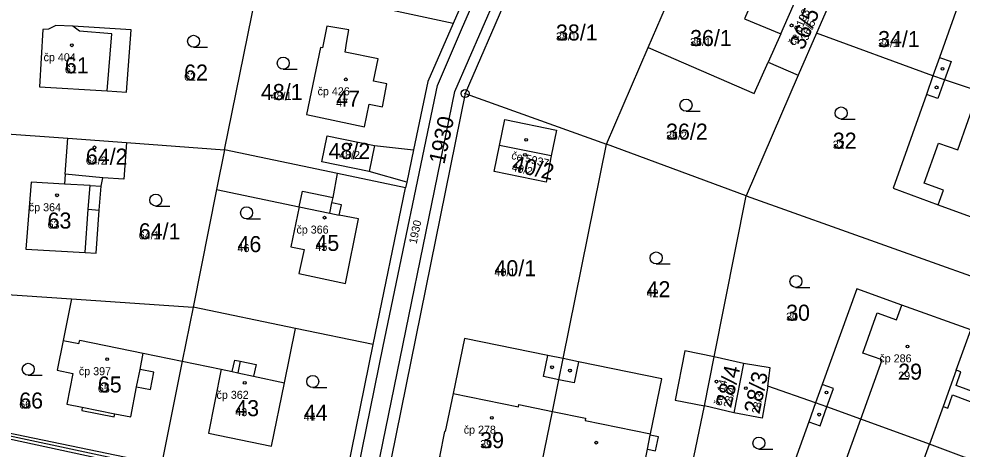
# Model space of a CAD drawing. Extents: x -763628 to -761565, y -976033 to -973833.
# Drawn here: x -762540.9 to -762423.1, y -974916.1 to -974862.4 of the extents above; entities that cross this region are included whole.
import ezdxf

# ---------------------------------------------------------------- set-up
doc = ezdxf.new("R2010")
doc.units = 0
for name, color, linetype in [('KN_cisla parcel 1000', 7, 'Continuous'), ('KN_cisla parcel 500', 7, 'Continuous'), ('KN_cisla popisna 500', 7, 'Continuous'), ('KN_hranice parcel', 7, 'Continuous'), ('KN_vecna bremena', 7, 'Continuous'), ('KN_vnitrni kresba parcel', 7, 'Continuous'), ('KN_znacky bodu BP', 7, 'Continuous'), ('KN_znacky budov', 7, 'Continuous'), ('KN_znacky kultur', 7, 'Continuous')]:
    doc.layers.add(name, color=color, linetype=linetype)

msp = doc.modelspace()

# ---------------------------------------------------------------- linework, layer by layer
at = {"layer": 'KN_hranice parcel'}
for p, q in [((-762479.49, -974846.12), (-762486.68, -974862.98)), ((-762475.48, -974849.36), (-762485.19, -974871.73)), ((-762462.34, -974865.99), (-762457.65, -974855.12)), ((-762486.68, -974862.98), (-762510.87, -974857.78)), ((-762445.75, -974864.29), (-762443.41, -974858.87)), ((-762515.26, -974878.75), (-762511.23, -974859.12)), ((-762439.69, -974860.48), (-762441.33, -974864.2)), ((-762445.75, -974864.29), (-762447.35, -974867.83)), ((-762441.33, -974864.2), (-762443.6, -974869.45)), ((-762426.77, -974869.52), (-762441.33, -974864.2)), ((-762467.55, -974878.06), (-762462.34, -974865.99)), ((-762447.35, -974867.83), (-762443.6, -974869.45)), ((-762443.6, -974869.45), (-762450.11, -974884.49)), ((-762485.19, -974871.73), (-762467.55, -974878.06)), ((-762543.9, -974876.64), (-762534.82, -974877.31)), ((-762535.16, -974881.79), (-762534.82, -974877.31)), ((-762534.82, -974877.31), (-762527.47, -974877.85)), ((-762527.47, -974877.85), (-762515.26, -974878.75)), ((-762515.26, -974878.75), (-762516.25, -974883.71)), ((-762501.13, -974881.7), (-762515.26, -974878.75)), ((-762491.64, -974878.76), (-762492.48, -974882.79)), ((-762472.96, -974904.8), (-762467.55, -974878.06)), ((-762450.11, -974884.49), (-762467.55, -974878.06)), ((-762530.44, -974882.24), (-762535.16, -974881.79)), ((-762492.63, -974883.48), (-762501.13, -974881.7)), ((-762516.25, -974883.71), (-762519.16, -974898.38)), ((-762496.67, -974903.06), (-762492.63, -974883.48)), ((-762492.48, -974882.79), (-762492.63, -974883.48)), ((-762454.1, -974904.59), (-762450.11, -974884.49)), ((-762545.41, -974896.62), (-762534.35, -974897.36)), ((-762534.35, -974897.36), (-762519.16, -974898.38)), ((-762519.16, -974898.38), (-762520.53, -974905.14)), ((-762506.36, -974901.04), (-762519.16, -974898.38)), ((-762496.67, -974903.06), (-762506.36, -974901.04)), ((-762500.67, -974922.63), (-762496.67, -974903.06)), ((-762455.32, -974910.72), (-762454.1, -974904.59)), ((-762450.45, -974905.4), (-762454.1, -974904.59)), ((-762520.53, -974905.14), (-762523.11, -974918.01)), ((-762450.45, -974905.4), (-762451.62, -974911.57)), ((-762441.42, -974910.33), (-762447.37, -974908.26)), ((-762451.62, -974911.57), (-762455.32, -974910.72)), ((-762544.15, -974913.69), (-762523.11, -974918.01))]:
    msp.add_line(p, q, dxfattribs=at)
for points in [[(-762404.96, -974868.77), (-762405.38, -974868.62), (-762409.21, -974867.24), (-762408.62, -974865.59), (-762409.16, -974865.4), (-762407.37, -974860.41), (-762416.04, -974857.29), (-762421.71, -974855.24), (-762425.95, -974867.22), (-762426.77, -974869.52)], [(-762448.77, -974858.83), (-762450.32, -974862.42), (-762445.75, -974864.29)], [(-762529.88, -974871.4), (-762527.49, -974871.55), (-762526.89, -974863.78), (-762534.19, -974863.34), (-762536.29, -974863.22), (-762537.23, -974863.71), (-762537.93, -974863.74), (-762538.36, -974870.89), (-762529.88, -974871.4)], [(-762499.96, -974865.2), (-762499.73, -974863.77), (-762502.46, -974863.34), (-762502.99, -974866.03), (-762503.26, -974865.97), (-762505.01, -974874.36), (-762497.75, -974875.88), (-762497.19, -974873.05), (-762495.53, -974873.38), (-762494.96, -974870.51), (-762496.62, -974870.18), (-762496.07, -974867.4), (-762500.18, -974866.56), (-762499.96, -974865.2)], [(-762486.68, -974862.98), (-762489.84, -974870.22), (-762491.64, -974878.76)], [(-762462.34, -974865.99), (-762449.11, -974871.74), (-762447.35, -974867.83)], [(-762426.77, -974869.52), (-762427.59, -974871.83), (-762431.74, -974883.56), (-762426.11, -974885.61), (-762417.54, -974888.75), (-762415.74, -974883.73), (-762415.19, -974883.93), (-762414.61, -974882.32), (-762410.79, -974883.63), (-762410.37, -974883.78)], [(-762407.64, -974876.21), (-762408.06, -974876.06), (-762412.43, -974874.5), (-762421.08, -974871.44), (-762425.33, -974870.03), (-762426.77, -974869.52)], [(-762485.19, -974871.73), (-762495.68, -974923.43), (-762495.72, -974923.63)], [(-762473.78, -974876.29), (-762474.43, -974879.52), (-762475.09, -974882.77), (-762481.56, -974881.46), (-762480.9, -974878.21), (-762480.24, -974874.97), (-762473.78, -974876.29)], [(-762492.48, -974882.79), (-762497.17, -974881.48), (-762503.09, -974880.25), (-762502.44, -974877.01), (-762496.53, -974878.21), (-762491.64, -974878.76)], [(-762527.47, -974877.85), (-762527.81, -974882.43), (-762530.44, -974882.24)], [(-762535.16, -974881.79), (-762535.23, -974883.03), (-762539.37, -974882.79), (-762540.06, -974891.15), (-762532.65, -974891.56), (-762531.28, -974891.64), (-762530.88, -974886.28), (-762530.65, -974883.29), (-762530.44, -974882.24)], [(-762516.25, -974883.71), (-762505.9, -974885.85), (-762506.97, -974890.84), (-762505.31, -974891.19), (-762505.95, -974894.2), (-762500.15, -974895.42), (-762498.51, -974887.38), (-762500.91, -974886.92), (-762500.63, -974885.63), (-762501.83, -974885.37), (-762501.69, -974884.72), (-762501.13, -974881.7)], [(-762450.11, -974884.49), (-762415.55, -974896.83), (-762415.13, -974896.98)], [(-762419.7, -974909.69), (-762420.13, -974909.53), (-762423.89, -974908.15), (-762423.28, -974906.48), (-762423.87, -974906.27), (-762422.04, -974901.23), (-762430.66, -974898.14), (-762436.29, -974896.12), (-762440.59, -974908.04), (-762441.42, -974910.33)], [(-762534.35, -974897.36), (-762535.4, -974902.54), (-762536.14, -974906.25), (-762534.18, -974906.65), (-762534.95, -974910.48), (-762533, -974910.87), (-762533.08, -974911.27), (-762529.02, -974912.09), (-762528.94, -974911.69), (-762526.96, -974912.09), (-762526.22, -974908.34), (-762524.49, -974908.68), (-762524.05, -974906.49), (-762525.79, -974906.15), (-762525.39, -974904.15), (-762520.53, -974905.14)], [(-762520.53, -974905.14), (-762515.67, -974906.14), (-762517.25, -974914.13), (-762509.37, -974915.75), (-762507.75, -974907.83), (-762506.36, -974901.04)], [(-762472.96, -974904.8), (-762474.88, -974904.41), (-762485.29, -974902.29), (-762486.7, -974909.15), (-762487.68, -974913.92), (-762487.76, -974913.9), (-762488.41, -974917.05), (-762485.24, -974917.71), (-762485.22, -974917.61), (-762480.68, -974918.54), (-762480.69, -974918.64), (-762477.19, -974919.36), (-762477.17, -974919.26), (-762475.93, -974919.52)], [(-762475.93, -974919.52), (-762474.29, -974911.39), (-762473.49, -974907.45), (-762472.96, -974904.8)], [(-762475.93, -974919.52), (-762474.79, -974919.75), (-762474.81, -974919.85), (-762471.28, -974920.58), (-762471.27, -974920.48), (-762466.74, -974921.41), (-762466.76, -974921.51), (-762463.6, -974922.16), (-762462.95, -974919.01), (-762463.02, -974918.99), (-762462.43, -974916.1), (-762461.41, -974916.31), (-762461.05, -974914.57), (-762462.07, -974914.36), (-762462.04, -974914.21), (-762460.61, -974907.32), (-762471.03, -974905.2), (-762472.96, -974904.8)], [(-762447.37, -974908.26), (-762447.09, -974905.96), (-762450.45, -974905.4)], [(-762447.37, -974908.26), (-762448.1, -974912.24), (-762451.62, -974911.57)], [(-762459.55, -974931.16), (-762459.51, -974930.94), (-762459.46, -974930.7), (-762455.32, -974910.72)], [(-762441.42, -974910.33), (-762442.27, -974912.68), (-762446.57, -974924.58), (-762440.92, -974926.61), (-762432.36, -974929.66), (-762430.52, -974924.59), (-762429.94, -974924.81), (-762429.34, -974923.14), (-762425.51, -974924.45), (-762425.07, -974924.6)], [(-762422.42, -974917.24), (-762422.86, -974917.09), (-762427.22, -974915.48), (-762435.78, -974912.35), (-762440.01, -974910.84), (-762441.42, -974910.33)]]:
    msp.add_lwpolyline(points, dxfattribs=at)
at = {"layer": 'KN_vecna bremena'}
for points in [[(-762542.29, -974914.78), (-762523.23, -974918.88)], [(-762523.16, -974918.54), (-762542.21, -974914.44)]]:
    msp.add_lwpolyline(points, dxfattribs=at)
at = {"layer": 'KN_vnitrni kresba parcel'}
for p, q in [((-762485.52, -974863.45), (-762468.88, -974825.29)), ((-762486.47, -974871.48), (-762467.08, -974826.74)), ((-762533.34, -974863.95), (-762534.19, -974863.34)), ((-762488.65, -974870.71), (-762485.52, -974863.45)), ((-762529.32, -974864.26), (-762533.34, -974863.95)), ((-762529.88, -974871.4), (-762529.32, -974864.26)), ((-762425.95, -974867.22), (-762424.51, -974867.73)), ((-762424.51, -974867.73), (-762425.33, -974870.03)), ((-762495.42, -974903.26), (-762488.65, -974870.71)), ((-762425.33, -974870.03), (-762426.15, -974872.35)), ((-762497.11, -974923.35), (-762486.47, -974871.48)), ((-762426.15, -974872.35), (-762427.59, -974871.83)), ((-762423.68, -974878.76), (-762421.08, -974871.44)), ((-762496.53, -974878.21), (-762497.17, -974881.48)), ((-762474.43, -974879.52), (-762480.9, -974878.21)), ((-762427.85, -974882.92), (-762426.07, -974877.91)), ((-762426.07, -974877.91), (-762423.68, -974878.76)), ((-762532.03, -974883.21), (-762535.23, -974883.03)), ((-762532.27, -974886.17), (-762532.03, -974883.21)), ((-762532.03, -974883.21), (-762530.65, -974883.29)), ((-762425.46, -974883.77), (-762427.85, -974882.92)), ((-762505.9, -974885.85), (-762505.49, -974883.91)), ((-762505.49, -974883.91), (-762501.69, -974884.72)), ((-762426.11, -974885.61), (-762425.46, -974883.77)), ((-762505.9, -974885.85), (-762502.11, -974886.66)), ((-762502.11, -974886.66), (-762501.83, -974885.37)), ((-762532.65, -974891.56), (-762532.27, -974886.17)), ((-762532.27, -974886.17), (-762530.88, -974886.28)), ((-762502.11, -974886.66), (-762500.91, -974886.92)), ((-762431.32, -974899.97), (-762430.66, -974898.14)), ((-762435.53, -974904.12), (-762433.72, -974899.1)), ((-762433.72, -974899.1), (-762431.32, -974899.97)), ((-762535.4, -974902.54), (-762533.42, -974902.94)), ((-762533.42, -974902.94), (-762533.33, -974902.5)), ((-762533.33, -974902.5), (-762525.39, -974904.15)), ((-762499.42, -974922.88), (-762495.42, -974903.26)), ((-762475.41, -974907.06), (-762474.88, -974904.41)), ((-762457.76, -974903.86), (-762458.98, -974909.99)), ((-762454.1, -974904.59), (-762457.76, -974903.86)), ((-762433.13, -974904.98), (-762435.53, -974904.12)), ((-762514.27, -974906.43), (-762513.96, -974904.99)), ((-762513.96, -974904.99), (-762513.27, -974905.14)), ((-762513.27, -974905.14), (-762513.58, -974906.58)), ((-762513.27, -974905.14), (-762511.3, -974905.56)), ((-762511.3, -974905.56), (-762511.61, -974907)), ((-762471.03, -974905.2), (-762471.57, -974907.84)), ((-762435.78, -974912.35), (-762433.13, -974904.98)), ((-762526.22, -974908.34), (-762525.79, -974906.15)), ((-762515.67, -974906.14), (-762514.27, -974906.43)), ((-762514.27, -974906.43), (-762513.58, -974906.58)), ((-762513.58, -974906.58), (-762511.61, -974907)), ((-762511.61, -974907), (-762507.75, -974907.83)), ((-762473.49, -974907.45), (-762475.41, -974907.06)), ((-762423.87, -974906.27), (-762425.51, -974910.8)), ((-762471.57, -974907.84), (-762473.49, -974907.45)), ((-762439.18, -974908.55), (-762440.59, -974908.04)), ((-762486.7, -974909.15), (-762478.54, -974910.82)), ((-762440.01, -974910.84), (-762439.18, -974908.55)), ((-762424.93, -974911.01), (-762424.33, -974909.35)), ((-762424.33, -974909.35), (-762420.57, -974910.75)), ((-762478.54, -974910.82), (-762478.48, -974910.53)), ((-762478.48, -974910.53), (-762474.29, -974911.39)), ((-762458.98, -974909.99), (-762455.32, -974910.72)), ((-762425.51, -974910.8), (-762427.22, -974915.48)), ((-762425.51, -974910.8), (-762424.93, -974911.01)), ((-762533, -974910.87), (-762528.94, -974911.69)), ((-762474.29, -974911.39), (-762470.16, -974912.24)), ((-762440.85, -974913.2), (-762440.01, -974910.84)), ((-762470.16, -974912.24), (-762470.22, -974912.53)), ((-762470.22, -974912.53), (-762462.04, -974914.21)), ((-762442.27, -974912.68), (-762440.85, -974913.2)), ((-762438.43, -974919.69), (-762435.78, -974912.35)), ((-762462.43, -974916.1), (-762462.07, -974914.36)), ((-762428.88, -974920.07), (-762427.22, -974915.48))]:
    msp.add_line(p, q, dxfattribs=at)
at = {"layer": 'KN_znacky bodu BP'}
for radius in [0.5, 0.0303]:
    msp.add_circle((-762485.19, -974871.73), radius, dxfattribs=at)
at = {"layer": 'KN_znacky budov'}
for centre in [(-762444.42, -974863.22), (-762534.32, -974865.71), (-762425.58, -974868.64), (-762500.1, -974869.96), (-762426.31, -974870.96), (-762477.57, -974877.51), (-762531.48, -974878.45), (-762499.53, -974878.11), (-762477.72, -974879.38), (-762536.16, -974884.43), (-762502.74, -974887.22), (-762429.94, -974903.29), (-762529.91, -974904.89), (-762474.34, -974905.89), (-762472.1, -974906.31), (-762512.72, -974907.84), (-762453.81, -974907.68), (-762450.14, -974908.5), (-762440.07, -974909.05), (-762440.98, -974911.8), (-762481.85, -974912.19), (-762468.81, -974915.3)]:
    msp.add_circle(centre, 0.175, dxfattribs=at)
at = {"layer": 'KN_znacky kultur'}
for p, q in [((-762519.1, -974865.96), (-762517.35, -974865.96)), ((-762507.91, -974868.69), (-762506.16, -974868.69)), ((-762457.61, -974873.93), (-762455.86, -974873.93)), ((-762438.23, -974874.91), (-762436.48, -974874.91)), ((-762523.83, -974885.77), (-762522.08, -974885.77)), ((-762512.49, -974887.37), (-762510.74, -974887.37)), ((-762461.34, -974893), (-762459.59, -974893)), ((-762443.88, -974895.93), (-762442.13, -974895.93)), ((-762539.75, -974906.89), (-762538, -974906.89)), ((-762504.22, -974908.42), (-762502.47, -974908.42)), ((-762448.51, -974916.1), (-762446.76, -974916.1))]:
    msp.add_line(p, q, dxfattribs=at)
for centre in [(-762519.1, -974865.21), (-762507.91, -974867.94), (-762457.61, -974873.18), (-762438.23, -974874.16), (-762523.83, -974885.02), (-762512.49, -974886.62), (-762461.34, -974892.25), (-762443.88, -974895.18), (-762539.75, -974906.14), (-762504.22, -974907.67), (-762448.51, -974915.35)]:
    msp.add_circle(centre, 0.75, dxfattribs=at)

# ---------------------------------------------------------------- texts
at = {"layer": 'KN_cisla parcel 1000'}
for s, rotation, p in [('36/5', 67, (-762442.94, -974866.4)), ('1930', 78, (-762487.79, -974880.64)), ('40/2', 347, (-762479.44, -974881.38)), ('28/4', 77, (-762451.98, -974911.01)), ('28/3', 78, (-762448.44, -974911.77))]:
    msp.add_text(s, height=2, rotation=rotation, dxfattribs=at).set_placement(p)
for s, p in [('38/1', (-762473.85, -974865.11)), ('36/1', (-762457.1, -974865.8)), ('34/1', (-762433.62, -974865.93)), ('61', (-762535.18, -974869.21)), ('62', (-762520.29, -974870.11)), ('48/1', (-762510.7, -974872.54)), ('47', (-762501.3, -974873.37)), ('36/2', (-762460.1, -974877.48)), ('32', (-762439.28, -974878.61)), ('48/2', (-762502.25, -974879.9)), ('64/2', (-762532.56, -974880.6)), ('63', (-762537.34, -974888.58)), ('64/1', (-762525.95, -974889.92)), ('46', (-762513.62, -974891.52)), ('45', (-762503.89, -974891.37)), ('40/1', (-762481.53, -974894.53)), ('42', (-762462.53, -974897.15)), ('30', (-762445.11, -974900.08)), ('29', (-762431.11, -974907.44)), ('65', (-762531.06, -974909.04)), ('66', (-762540.88, -974911.04)), ('43', (-762513.9, -974911.99)), ('44', (-762505.35, -974912.57)), ('39', (-762483.31, -974915.98))]:
    msp.add_text(s, height=2, dxfattribs=at).set_placement(p)
at = {"layer": 'KN_cisla parcel 500'}
for s, rotation, p in [('36/5', 67, (-762442.42, -974865.19)), ('40/2', 347, (-762479.44, -974881.38)), ('1930', 78, (-762491.26, -974890.56)), ('28/4', 77, (-762451.98, -974911.01)), ('28/3', 78, (-762448.44, -974911.77))]:
    msp.add_text(s, height=1, rotation=rotation, dxfattribs=at).set_placement(p)
for s, p in [('38/1', (-762473.85, -974865.11)), ('36/1', (-762457.1, -974865.8)), ('34/1', (-762433.62, -974865.93)), ('61', (-762535.18, -974869.21)), ('62', (-762520.29, -974870.11)), ('48/1', (-762509.48, -974872.54)), ('47', (-762501.3, -974873.37)), ('36/2', (-762460.1, -974877.48)), ('32', (-762439.28, -974878.61)), ('48/2', (-762500.93, -974879.9)), ('64/2', (-762532.56, -974880.6)), ('63', (-762537.34, -974888.58)), ('64/1', (-762525.95, -974889.92)), ('46', (-762513.62, -974891.52)), ('45', (-762503.89, -974891.37)), ('40/1', (-762481.53, -974894.53)), ('42', (-762462.53, -974897.15)), ('30', (-762445.11, -974900.08)), ('29', (-762431.11, -974907.44)), ('65', (-762531.06, -974909.04)), ('66', (-762540.88, -974911.04)), ('43', (-762513.9, -974911.99)), ('44', (-762505.35, -974912.57)), ('39', (-762483.31, -974915.98))]:
    msp.add_text(s, height=1, dxfattribs=at).set_placement(p)
at = {"layer": 'KN_cisla popisna 500'}
for s, rotation, p in [('če 6193', 67, (-762443.98, -974865.82)), ('če 5937', 347, (-762479.49, -974879.88)), ('če 14', 77, (-762453.19, -974910.76))]:
    msp.add_text(s, height=1, rotation=rotation, dxfattribs=at).set_placement(p)
for s, p in [('čp 404', (-762537.84, -974867.7)), ('čp 426', (-762503.62, -974871.95)), ('čp 364', (-762539.68, -974886.42)), ('čp 366', (-762506.26, -974889.21)), ('čp 286', (-762433.46, -974905.28)), ('čp 397', (-762533.43, -974906.88)), ('čp 362', (-762516.24, -974909.83)), ('čp 278', (-762485.37, -974914.18))]:
    msp.add_text(s, height=1, dxfattribs=at).set_placement(p)

doc.saveas('drawing.dxf')
